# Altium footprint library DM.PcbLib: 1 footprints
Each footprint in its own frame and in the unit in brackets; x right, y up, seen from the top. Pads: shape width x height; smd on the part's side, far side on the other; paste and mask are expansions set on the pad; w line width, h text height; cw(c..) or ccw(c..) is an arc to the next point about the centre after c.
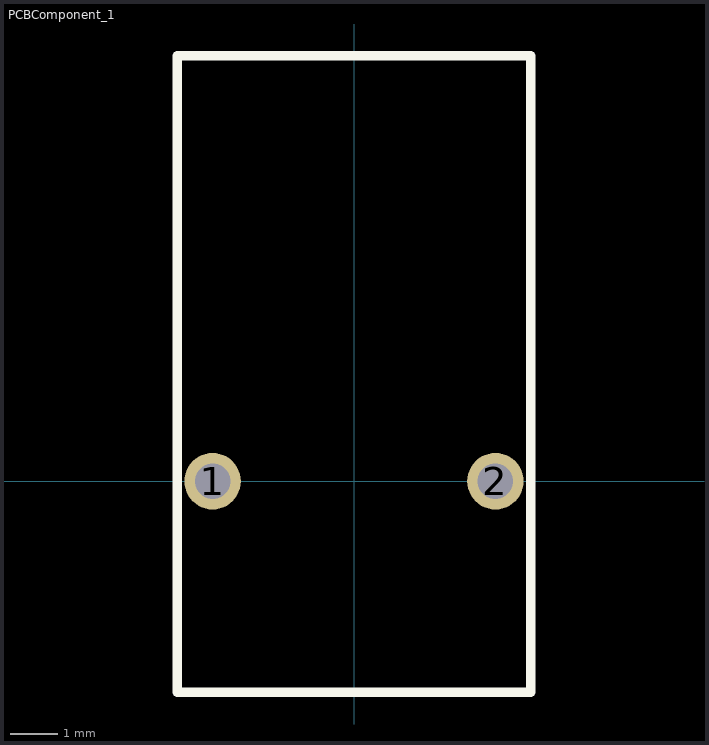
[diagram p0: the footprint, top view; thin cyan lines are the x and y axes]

## PCBComponent_1 [mm]
pads (2):
  round 1.2 hole 0.75: 1(-3,0) 2(3,0)
Top Overlay:
  lines w0.2: -3.75,-4.475 -3.75,9.025 3.75,9.025 3.75,-4.475 -3.75,-4.475
M5 Assembly Top:
  text ".Designator" at -2,-0.7 h1.85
